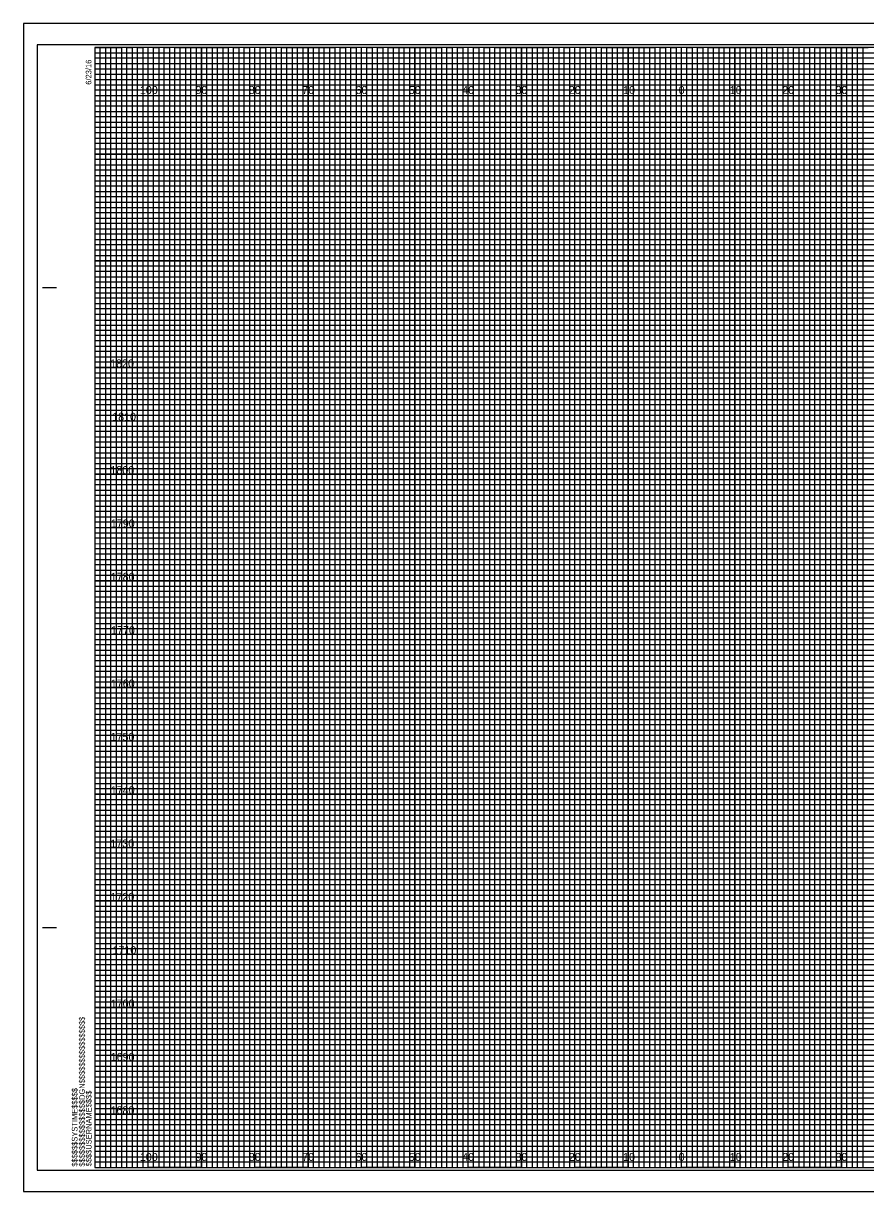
# Model space of a CAD drawing. Extents: x -419 to 4739, y -630 to 13534.
# Drawn here: x 839.6 to 997.5, y 439 to 658 of the extents above; entities that cross this region are included whole.
import ezdxf

# ---------------------------------------------------------------- set-up
doc = ezdxf.new("R2010")
doc.units = 0
for name, color, linetype in [('Old_Level_62', 7, 'Continuous'), ('Pattern 1', 7, 'Continuous'), ('Pattern 18', 7, 'Continuous'), ('Pattern 4', 7, 'Continuous'), ('Pattern 5', 7, 'Continuous'), ('Prop Dimension', 7, 'Continuous'), ('Prop Horizontal Alignment', 7, 'Continuous'), ('Raster_Level_0', 7, 'Continuous'), ('Scratch_Level_0', 7, 'Continuous'), ('Scratch_Level_3', 7, 'Continuous'), ('Scratch_Level_5', 7, 'Continuous')]:
    doc.layers.add(name, color=color, linetype=linetype)

msp = doc.modelspace()

# ---------------------------------------------------------------- linework, layer by layer
at = {"layer": 'Old_Level_62'}
for p, q in [((843.25, 608.49), (845.75, 608.49)), ((843.35, 608.49), (845.85, 608.49)), ((843.25, 488.49), (845.75, 488.49)), ((843.35, 488.49), (845.85, 488.49)), ((853.05, 443.49), (853.05, 443.49)), ((853.05, 443.49), (853.05, 443.49)), ((853.05, 443.49), (853.05, 443.49)), ((853.05, 443.49), (853.05, 443.49)), ((853.05, 443.49), (853.05, 443.49)), ((853.05, 443.49), (853.05, 443.49)), ((853.05, 443.49), (853.05, 443.49))]:
    msp.add_line(p, q, dxfattribs=at)
msp.add_lwpolyline([(1173.05, 653.49), (853.05, 653.49), (853.05, 443.49), (1173.05, 443.49)], close=True, dxfattribs=at)
at = {"layer": 'Pattern 18'}
msp.add_lwpolyline([(839.65, 438.99), (1176.35, 438.99), (1176.35, 657.99), (839.65, 657.99)], close=True, dxfattribs=at)
at = {"layer": 'Pattern 4'}
for p, q in [((853.05, 652.49), (1113.05, 652.49)), ((1113.05, 651.47), (853.05, 651.47)), ((853.05, 651.47), (853.05, 650.49)), ((853.05, 650.49), (1113.05, 650.49)), ((1113.05, 649.38), (853.05, 649.38)), ((853.05, 649.38), (853.05, 647.49)), ((853.05, 647.49), (1173.05, 647.49))]:
    msp.add_line(p, q, dxfattribs=at)
for points in [[(853.05, 646.49), (1123.05, 646.49), (1173.05, 646.49), (1173.05, 645.49), (853.05, 645.49)], [(853.05, 644.49), (1173.05, 644.49), (1173.05, 642.49), (853.05, 642.49)], [(853.05, 641.49), (1173.05, 641.49), (1173.05, 640.49), (853.05, 640.47)], [(853.05, 639.49), (1173.05, 639.49), (1173.05, 637.49), (853.05, 637.49)], [(853.05, 636.49), (1173.05, 636.49), (1173.05, 635.49), (853.05, 635.49)], [(853.05, 634.49), (1173.05, 634.49), (1173.05, 632.49), (853.05, 632.49)], [(853.05, 631.49), (1173.05, 631.49), (1173.05, 630.49), (853.05, 630.49)], [(853.05, 629.49), (1173.05, 629.49), (1173.05, 627.49), (853.05, 627.49)], [(853.05, 626.49), (1173.05, 626.49), (1173.05, 625.49), (853.05, 625.49)], [(853.05, 624.49), (1173.05, 624.49), (1173.05, 622.49), (853.05, 622.49)], [(853.05, 621.49), (1173.05, 621.49), (1173.05, 620.49), (853.05, 620.49)], [(853.05, 619.49), (1173.05, 619.49), (1173.05, 617.44), (1173.05, 616.49), (1173.05, 615.49), (853.05, 615.49)], [(853.05, 617.49), (1173.05, 617.49), (1173.05, 616.49), (853.05, 616.49)], [(853.05, 614.49), (1173.05, 614.49), (1173.05, 612.49), (853.05, 612.52)], [(853.05, 612.52), (1173.05, 612.49), (1173.05, 611.49), (853.05, 611.49)], [(853.05, 610.49), (1173.05, 610.49), (1173.05, 609.49), (853.05, 609.49)], [(853.05, 607.49), (1173.05, 607.49), (1173.05, 606.49), (853.05, 606.49)], [(853.05, 605.49), (1173.05, 605.49), (1173.05, 604.49), (853.05, 604.49)], [(852.98, 602.38), (1173.05, 602.38), (1173.05, 601.37), (852.98, 601.37)], [(853.05, 600.49), (1173.05, 600.49), (1173.05, 599.49), (853.05, 599.49)], [(853.05, 597.49), (1173.05, 597.49), (1173.05, 596.49), (853.05, 596.49)], [(853.05, 595.49), (1173.05, 595.49), (1173.05, 594.49), (853.05, 594.49)], [(853.05, 592.49), (1173.05, 592.49), (1173.05, 591.49), (853.05, 591.49)], [(853.05, 590.49), (1173.05, 590.49), (1173.05, 589.49), (853.05, 589.49)], [(853.05, 587.49), (1173.05, 587.49), (1173.05, 586.49), (853.05, 586.49)], [(853.05, 585.49), (1173.05, 585.49), (1173.05, 584.49), (853.05, 584.49)], [(853.05, 582.49), (1173.05, 582.49), (1173.04, 581.47), (853.05, 581.49)], [(853.05, 580.49), (1173.05, 580.49), (1173.05, 579.49), (853.05, 579.49)], [(853.05, 577.49), (1173.05, 577.49), (1173.05, 576.49), (853.05, 576.49)], [(853.05, 575.49), (1173.05, 575.49), (1173.05, 574.49), (853.05, 574.49)], [(853.05, 572.49), (1173.05, 572.49), (1173.05, 571.49), (853.05, 571.49)], [(853.05, 570.49), (1173.05, 570.49), (1173.05, 569.49), (853.05, 569.49)], [(853.05, 567.49), (1173.05, 567.49), (1173.05, 566.49), (853.05, 566.49)], [(853.05, 565.49), (1173.05, 565.49), (1173.05, 564.49), (853.05, 564.49)], [(853.05, 562.49), (1173.05, 562.49), (1173.05, 561.49), (853.05, 561.49)], [(853.05, 560.48), (1173.12, 560.4), (1173.05, 559.49), (853.05, 559.49)], [(853.05, 557.49), (1173.05, 557.49), (1173.05, 556.49), (853.05, 556.49)], [(853.05, 555.49), (1173.05, 555.49), (1173.05, 554.49), (853.05, 554.49)], [(853.05, 552.49), (1173.05, 552.49), (1173.05, 551.49), (853.05, 551.49)], [(853.05, 550.49), (1173.05, 550.49), (1173.05, 549.49), (853.05, 549.49)], [(853.05, 547.49), (1173.05, 547.49), (1173.05, 546.49), (853.05, 546.49)], [(853.05, 545.49), (1173.05, 545.49), (1173.05, 544.49), (853.05, 544.49)], [(853.05, 542.49), (1173.05, 542.49), (1173.05, 541.49), (853.05, 541.49)], [(853.05, 540.49), (1173.05, 540.49), (1173.05, 539.49), (853.05, 539.49)], [(853.05, 537.49), (1173.05, 537.49), (1173.05, 536.49), (853.05, 536.49)], [(853.05, 535.49), (1173.05, 535.49), (1173.05, 534.49), (853.05, 534.49)], [(853.05, 532.49), (1173.05, 532.49), (1173.05, 531.49), (853.05, 531.49)], [(853.05, 530.49), (1173.05, 530.49), (1173.05, 529.49), (853.05, 529.49)], [(853.05, 527.49), (1173.05, 527.49), (1173.05, 526.49), (853.05, 526.49)], [(853.05, 525.49), (1173.05, 525.49), (1173.05, 524.49), (853.05, 524.49)], [(853.05, 522.49), (1173.05, 522.49), (1173.04, 521.47), (853.05, 521.49)], [(853.05, 520.49), (1173.05, 520.49), (1173.05, 519.49), (853.05, 519.49)], [(853.05, 517.49), (1173.05, 517.49), (1173.05, 516.49), (853.05, 516.49)], [(853.05, 515.49), (1173.05, 515.49), (1173.05, 514.49), (853.05, 514.49)], [(853.05, 512.49), (1173.05, 512.49), (1173.05, 511.49), (853.05, 511.49)], [(853.05, 510.49), (1173.05, 510.49), (1173.05, 509.49), (853.05, 509.49)], [(853.05, 507.49), (1173.05, 507.49), (1173.05, 506.49), (853.05, 506.49)], [(853.05, 505.49), (1173.05, 505.49), (1173.05, 504.49), (853.05, 504.49)], [(853.05, 502.49), (1173.05, 502.49), (1173.05, 501.49), (853.05, 501.49)], [(853.05, 500.48), (1173.12, 500.4), (1173.05, 499.49), (853.05, 499.49)], [(853.05, 497.49), (1173.05, 497.49), (1173.05, 496.49), (853.05, 496.49)], [(853.05, 495.49), (1173.05, 495.49), (1173.05, 494.49), (853.05, 494.49)], [(853.05, 492.49), (1173.05, 492.49), (1173.05, 491.49), (853.05, 491.49)], [(853.05, 490.49), (1173.05, 490.49), (1173.05, 489.49), (853.05, 489.49)], [(853.05, 487.49), (1173.05, 487.49), (1173.05, 486.49), (853.05, 486.49)], [(853.05, 485.49), (1173.05, 485.49), (1173.05, 484.49), (853.05, 484.49)], [(853.05, 482.49), (1173.05, 482.49), (1173.05, 481.49), (853.05, 481.49)], [(853.05, 480.49), (1173.05, 480.49), (1173.05, 479.49), (853.05, 479.49)], [(853.05, 477.49), (1173.05, 477.49), (1173.05, 476.49), (853.05, 476.49)], [(853.05, 475.49), (1173.05, 475.49), (1173.05, 474.49), (853.05, 474.49)], [(853.05, 472.49), (1173.05, 472.49), (1173.05, 471.49), (853.05, 471.49)], [(853.05, 470.49), (1173.05, 470.49), (1173.05, 469.49), (853.05, 469.49)], [(853.05, 467.49), (1173.05, 467.49), (1173.05, 466.49), (853.05, 466.49)], [(853.05, 465.49), (1173.05, 465.49), (1173.05, 464.49), (853.05, 464.49)], [(853.05, 462.49), (1173.05, 462.49), (1173.05, 461.49), (853.05, 461.49)], [(853.05, 460.49), (1173.05, 460.49), (1173.05, 459.49), (853.05, 459.49)], [(853.05, 457.49), (1173.05, 457.49), (1173.05, 456.49), (853.05, 456.49)], [(853.05, 455.49), (1173.05, 455.49), (1173.05, 454.49), (853.05, 454.49)], [(853.05, 452.49), (1173.05, 452.49), (1173.05, 451.49), (853.05, 451.49)], [(853.05, 450.49), (1173.05, 450.49), (1173.05, 449.49), (853.05, 449.49)], [(853.05, 447.49), (1173.05, 447.49), (1173.05, 446.49), (853.05, 446.49)], [(853.05, 445.49), (1173.05, 445.49), (1173.05, 444.49), (853.05, 444.49)]]:
    msp.add_lwpolyline(points, dxfattribs=at)
at = {"layer": 'Pattern 5'}
for p, q in [((1176.35, 657.99), (839.65, 657.99)), ((839.65, 657.99), (839.65, 438.99)), ((839.65, 438.99), (1176.35, 438.99))]:
    msp.add_line(p, q, dxfattribs=at)
at = {"layer": 'Prop Dimension'}
for points in [[(853.05, 443.49), (854.05, 443.49), (854.05, 653.49), (855.05, 653.49), (855.05, 443.49)], [(855.05, 443.49), (856.05, 443.49), (856.05, 653.49), (857.05, 653.49), (857.05, 443.49)], [(858.05, 443.49), (859.05, 443.49), (859.05, 653.49), (860.05, 653.49), (860.05, 443.49)], [(860.05, 443.49), (861.05, 443.49), (861.05, 653.49), (862.05, 653.49), (862.05, 443.49)], [(863.05, 443.49), (864.05, 443.49), (864.05, 653.49), (865.05, 653.49), (865.05, 443.49)], [(865.05, 443.49), (866.05, 443.49), (866.05, 653.49), (867.05, 653.49), (867.05, 443.49)], [(868.05, 443.49), (869.05, 443.49), (869.05, 653.49), (870.05, 653.49), (870.05, 443.49)], [(870.05, 443.49), (871.05, 443.49), (871.05, 653.49), (872.05, 653.49), (872.05, 443.49)], [(873.05, 443.49), (874.05, 443.49), (874.05, 653.49), (875.05, 653.49), (875.05, 443.49)], [(875.05, 443.49), (876.05, 443.49), (876.05, 653.49), (877.05, 653.49), (877.05, 443.49)], [(878.05, 443.49), (879.05, 443.49), (879.05, 653.49), (880.05, 653.49), (880.05, 443.49)], [(880.05, 443.49), (881.05, 443.49), (881.05, 653.49), (882.05, 653.49), (882.05, 443.49)], [(883.05, 443.49), (884.05, 443.49), (884.05, 653.49), (885.05, 653.49), (885.05, 443.49)], [(885.05, 443.49), (886.05, 443.49), (886.05, 653.49), (887.05, 653.49), (887.05, 443.49)], [(888.05, 443.49), (889.05, 443.49), (889.05, 653.49), (890.05, 653.49), (890.05, 443.49)], [(890.05, 443.49), (891.05, 443.49), (891.05, 653.49), (892.05, 653.49), (892.05, 443.49)], [(893.05, 443.49), (894.05, 443.49), (894.05, 653.49), (895.05, 653.49), (895.05, 443.49)], [(895.05, 443.49), (896.05, 443.49), (896.05, 653.49), (897.05, 653.49), (897.05, 443.49)], [(898.05, 443.49), (899.05, 443.49), (899.05, 653.49), (900.05, 653.49), (900.05, 443.49)], [(900.05, 443.49), (901.05, 443.49), (901.05, 653.49), (902.05, 653.49), (902.05, 443.49)], [(903.05, 443.49), (904.05, 443.49), (904.05, 653.49), (905.05, 653.49), (905.05, 443.49)], [(905.05, 443.49), (906.05, 443.49), (906.05, 653.49), (907.05, 653.49), (907.05, 443.49)], [(908.05, 443.49), (909.05, 443.49), (909.05, 653.49), (910.05, 653.49), (910.05, 443.49)], [(910.05, 443.49), (911.05, 443.49), (911.05, 653.49), (912.05, 653.49), (912.05, 443.49)], [(913.05, 443.49), (914.05, 443.49), (914.05, 653.49), (915.05, 653.49), (915.05, 443.49)], [(915.05, 443.49), (916.05, 443.49), (916.05, 653.49), (917.05, 653.49), (917.05, 443.49)], [(918.05, 443.49), (919.05, 443.49), (919.05, 653.49), (920.05, 653.49), (920.05, 443.49)], [(920.05, 443.49), (921.05, 443.49), (921.05, 653.49), (922.05, 653.49), (922.05, 443.49)], [(923.05, 443.49), (924.05, 443.49), (924.05, 653.49), (925.05, 653.49), (925.05, 443.49)], [(925.05, 443.49), (926.05, 443.49), (926.05, 653.49), (927.05, 653.49), (927.05, 443.49)], [(928.05, 443.49), (929.05, 443.49), (929.05, 653.49), (930.05, 653.49), (930.05, 443.49)], [(930.05, 443.49), (931.05, 443.49), (931.05, 653.49), (932.05, 653.49), (932.05, 443.49)], [(933.05, 443.49), (934.05, 443.49), (934.05, 653.49), (935.05, 653.49), (935.05, 443.49)], [(935.05, 443.49), (936.05, 443.49), (936.05, 653.49), (937.05, 653.49), (937.05, 443.49)], [(938.05, 443.49), (939.05, 443.49), (939.05, 653.49), (940.05, 653.49), (940.05, 443.49)], [(940.05, 443.49), (941.05, 443.49), (941.05, 653.49), (942.05, 653.49), (942.05, 443.49)], [(943.05, 443.49), (944.05, 443.49), (944.05, 653.49), (945.05, 653.49), (945.05, 443.49)], [(945.05, 443.49), (946.05, 443.49), (946.05, 653.49), (947.05, 653.49), (947.05, 443.49)], [(948.05, 443.49), (949.05, 443.49), (949.05, 653.49), (950.05, 653.49), (950.05, 443.49)], [(950.05, 443.49), (951.05, 443.49), (951.05, 653.49), (952.05, 653.49), (952.05, 443.49)], [(953.05, 443.49), (954.05, 443.49), (954.05, 653.49), (955.05, 653.49), (955.05, 443.49)], [(955.05, 443.49), (956.05, 443.49), (956.05, 653.49), (957.05, 653.49), (957.05, 443.49)], [(958.05, 443.49), (959.05, 443.49), (959.05, 653.49), (960.05, 653.49), (960.05, 443.49)], [(960.05, 443.49), (961.05, 443.49), (961.05, 653.49), (962.05, 653.49), (962.05, 443.49)], [(963.05, 443.49), (964.05, 443.49), (964.05, 653.49), (965.05, 653.49), (965.05, 443.49)], [(965.05, 443.49), (966.05, 443.49), (966.05, 653.49), (967.05, 653.49), (967.05, 443.49)], [(968.05, 443.49), (969.05, 443.49), (969.05, 653.49), (970.05, 653.49), (970.05, 443.49)], [(970.05, 443.49), (971.05, 443.49), (971.05, 653.49), (972.05, 653.49), (972.05, 443.49)], [(973.05, 443.49), (974.05, 443.49), (974.05, 653.49), (975.05, 653.49), (975.05, 443.49)], [(975.05, 443.49), (976.05, 443.49), (976.05, 653.49), (977.05, 653.49), (977.05, 443.49)], [(978.05, 443.49), (979.05, 443.49), (979.05, 653.49), (980.05, 653.49), (980.05, 443.49)], [(980.05, 443.49), (981.05, 443.49), (981.05, 653.49), (982.05, 653.49), (982.05, 443.49)], [(983.05, 443.49), (984.05, 443.49), (984.05, 653.49), (985.05, 653.49), (985.05, 443.49)], [(985.05, 443.49), (986.05, 443.49), (986.05, 653.49), (987.05, 653.49), (987.05, 443.49)], [(988.05, 443.49), (989.05, 443.49), (989.05, 653.49), (990.05, 653.49), (990.05, 443.49)], [(990.05, 443.49), (991.05, 443.49), (991.05, 653.49), (992.05, 653.49), (992.05, 443.49)], [(993.05, 443.49), (994.05, 443.49), (994.05, 653.49), (995.05, 653.49), (995.05, 443.49)], [(995.05, 443.49), (996.05, 443.49), (996.05, 653.49), (997.05, 653.49), (997.05, 443.49)]]:
    msp.add_lwpolyline(points, dxfattribs=at)
at = {"layer": 'Prop Horizontal Alignment'}
for points in [[(853.05, 653.49), (858.05, 653.49), (858.05, 443.49), (868.05, 443.49), (868.05, 653.49), (878.05, 653.49), (878.05, 443.49), (888.05, 443.49), (888.05, 653.49), (898.05, 653.49), (898.05, 443.49), (908.05, 443.49), (908.05, 653.49), (918.05, 653.49), (918.05, 443.49), (928.05, 443.49), (928.05, 653.49), (938.05, 653.49), (938.05, 443.49), (948.05, 443.49), (948.05, 653.49), (958.05, 653.49), (958.05, 443.49), (968.05, 443.49), (968.05, 653.49), (978.05, 653.49), (978.05, 443.49), (988.05, 443.49), (988.05, 653.49), (998.05, 653.49)], [(853.05, 648.49), (1128.05, 648.49)], [(853.05, 628.49), (1173.05, 628.49), (1173.05, 638.49), (853.05, 638.49)], [(853.05, 608.49), (1173.05, 608.49), (1173.05, 618.49), (853.05, 618.49)], [(853.05, 588.49), (1173.05, 588.49), (1173.05, 598.49), (853.05, 598.49)], [(853.05, 568.49), (1173.05, 568.49), (1173.05, 578.49), (853.05, 578.49)], [(853.05, 548.49), (1173.05, 548.49), (1173.05, 558.49), (853.05, 558.49)], [(853.05, 528.49), (1173.05, 528.49), (1173.05, 538.49), (853.05, 538.49)], [(853.05, 508.49), (1173.05, 508.49), (1173.05, 518.49), (853.05, 518.49)], [(853.05, 488.49), (1173.05, 488.49), (1173.05, 498.49), (853.05, 498.49)], [(853.05, 468.49), (1173.05, 468.49), (1173.05, 478.49), (853.05, 478.49)], [(853.05, 448.49), (1173.05, 448.49), (1173.05, 458.49), (853.05, 458.49)]]:
    msp.add_lwpolyline(points, dxfattribs=at)
at = {"layer": 'Scratch_Level_0'}
for p, q in [((863.05, 443.49), (863.05, 653.49)), ((873.05, 443.49), (873.05, 653.49)), ((883.05, 443.49), (883.05, 653.49)), ((893.05, 443.49), (893.05, 653.49)), ((903.05, 443.49), (903.05, 653.49)), ((913.05, 443.49), (913.05, 653.49)), ((923.05, 443.49), (923.05, 653.49)), ((933.05, 443.49), (933.05, 653.49)), ((943.05, 443.49), (943.05, 653.49)), ((953.05, 443.49), (953.05, 653.49)), ((963.05, 443.49), (963.05, 653.49)), ((973.05, 443.49), (973.05, 653.49)), ((983.05, 443.49), (983.05, 653.49)), ((993.05, 443.49), (993.05, 653.49)), ((853.05, 643.49), (1173.05, 643.49)), ((853.05, 633.49), (1173.05, 633.49)), ((853.05, 623.49), (1173.05, 623.49)), ((853.05, 613.49), (1173.05, 613.49)), ((853.05, 603.49), (1173.05, 603.49)), ((853.05, 593.49), (1173.05, 593.49)), ((853.05, 583.49), (1173.05, 583.49)), ((853.05, 573.49), (1173.05, 573.49)), ((853.05, 563.49), (1173.05, 563.49)), ((853.05, 553.49), (1173.05, 553.49)), ((853.05, 543.49), (1173.05, 543.49)), ((853.05, 533.49), (1173.05, 533.49)), ((853.05, 523.49), (1173.05, 523.49)), ((853.05, 513.49), (1173.05, 513.49)), ((853.05, 503.49), (1173.05, 503.49)), ((853.05, 493.49), (1173.05, 493.49)), ((853.05, 483.49), (1173.05, 483.49)), ((853.05, 473.49), (1173.05, 473.49)), ((853.05, 463.49), (1173.05, 463.49)), ((853.05, 453.49), (1173.05, 453.49))]:
    msp.add_line(p, q, dxfattribs=at)
at = {"layer": 'Scratch_Level_3'}
for p, q in [((863.05, 653.49), (853.05, 653.49)), ((863.05, 443.49), (863.05, 653.49)), ((883.05, 653.49), (873.05, 653.49)), ((873.05, 653.49), (873.05, 443.49)), ((883.05, 443.49), (883.05, 653.49)), ((903.05, 653.49), (893.05, 653.49)), ((893.05, 653.49), (893.05, 443.49)), ((903.05, 443.49), (903.05, 653.49)), ((923.05, 653.49), (913.05, 653.49)), ((913.05, 653.49), (913.05, 443.49)), ((923.05, 443.49), (923.05, 653.49)), ((943.05, 653.49), (933.05, 653.49)), ((933.05, 653.49), (933.05, 443.49)), ((943.05, 443.49), (943.05, 653.49)), ((963.05, 653.49), (953.05, 653.49)), ((953.05, 653.49), (953.05, 443.49)), ((963.05, 443.49), (963.05, 653.49)), ((983.05, 653.49), (973.05, 653.49)), ((973.05, 653.49), (973.05, 443.49)), ((983.05, 443.49), (983.05, 653.49)), ((1003.05, 653.49), (993.05, 653.49)), ((993.05, 653.49), (993.05, 443.49)), ((873.05, 443.49), (863.05, 443.49)), ((893.05, 443.49), (883.05, 443.49)), ((913.05, 443.49), (903.05, 443.49)), ((933.05, 443.49), (923.05, 443.49)), ((953.05, 443.49), (943.05, 443.49)), ((973.05, 443.49), (963.05, 443.49)), ((993.05, 443.49), (983.05, 443.49))]:
    msp.add_line(p, q, dxfattribs=at)
for points in [[(853.05, 643.49), (1173.05, 643.49), (1173.05, 633.49), (853.05, 633.49)], [(853.05, 623.49), (1173.05, 623.49), (1173.05, 613.49), (853.05, 613.49)], [(853.05, 603.49), (1173.05, 603.49), (1173.05, 593.49), (853.05, 593.49)], [(853.05, 583.49), (1173.05, 583.49), (1173.05, 573.49), (853.05, 573.49)], [(853.05, 563.49), (1173.05, 563.49), (1173.05, 553.49), (853.05, 553.49)], [(853.05, 543.49), (1173.05, 543.49), (1173.05, 533.49), (853.05, 533.49)], [(853.05, 523.49), (1173.05, 523.49), (1173.05, 513.49), (853.05, 513.49)], [(853.05, 503.49), (1173.05, 503.49), (1173.05, 493.49), (853.05, 493.49)], [(853.05, 483.49), (1173.05, 483.49), (1173.05, 473.49), (853.05, 473.49)], [(853.05, 463.49), (1173.05, 463.49), (1173.05, 453.49), (853.05, 453.49)]]:
    msp.add_lwpolyline(points, dxfattribs=at)
at = {"layer": 'Scratch_Level_5'}
msp.add_lwpolyline([(842.25, 442.99), (1175.45, 442.99), (1175.45, 653.99), (842.25, 653.99)], close=True, dxfattribs=at)

# ---------------------------------------------------------------- texts
at = {"layer": 'Old_Level_62'}
for s, p in [('6/23/16', (852.4, 646.49)), ('$$$$$$$$$$$$$$$$DGN$$$$$$$$$$$$$$$$', (851.17, 443.67)), ('$$$$$$SYSTIME$$$$$', (849.79, 443.67)), ('$$$$USERNAME$$$$', (852.43, 443.72))]:
    msp.add_text(s, height=1.05, rotation=90, dxfattribs=at).set_placement(p)
at = {"layer": 'Pattern 1'}
for s, p in [('1820', (855.92, 593.49)), ('1810', (856.3, 583.49)), ('1800', (855.97, 573.49)), ('1790', (856.05, 563.49)), ('1780', (856.03, 553.49)), ('1770', (856.09, 543.49)), ('1760', (856.05, 533.49)), ('1750', (856, 523.49)), ('1740', (856.05, 513.49)), ('1730', (855.97, 503.49)), ('1720', (855.98, 493.49)), ('1710', (856.36, 483.49)), ('1700', (856.03, 473.49)), ('1690', (856.02, 463.49)), ('1680', (855.99, 453.49))]:
    msp.add_text(s, height=1.5, dxfattribs=at).set_placement(p)
at = {"layer": 'Raster_Level_0'}
for s, p in [('100', (861.49, 644.74)), ('90', (871.91, 644.74)), ('80', (881.91, 644.74)), ('70', (891.91, 644.74)), ('60', (901.91, 644.74)), ('50', (911.91, 644.74)), ('40', (921.91, 644.74)), ('30', (931.91, 644.74)), ('20', (941.91, 644.74)), ('10', (952.08, 644.74)), ('0', (962.5, 644.74)), ('0', (962.5, 644.74)), ('10', (972.08, 644.74)), ('20', (981.91, 644.74)), ('30', (991.91, 644.74)), ('100', (861.49, 444.74)), ('90', (871.91, 444.74)), ('80', (881.91, 444.74)), ('70', (891.91, 444.74)), ('60', (901.91, 444.74)), ('50', (911.91, 444.74)), ('40', (921.91, 444.74)), ('30', (931.91, 444.74)), ('20', (941.91, 444.74)), ('10', (952.08, 444.74)), ('0', (962.5, 444.74)), ('0', (962.5, 444.74)), ('10', (972.08, 444.74)), ('20', (981.91, 444.74)), ('30', (991.91, 444.74))]:
    msp.add_text(s, height=1.5, dxfattribs=at).set_placement(p)

doc.saveas('drawing.dxf')
